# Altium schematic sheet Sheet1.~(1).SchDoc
size A4
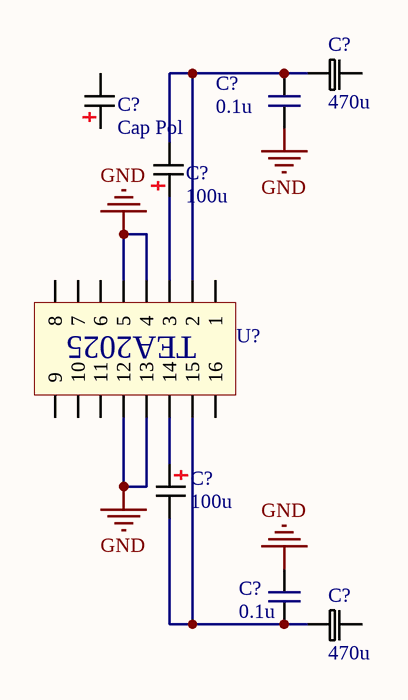
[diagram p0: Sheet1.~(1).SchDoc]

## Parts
(Parts that share a designator on the sheet are numbered #1, #2 ... from top to bottom, then left to right.)
C?#1  470u  [CF0.1]
C?#2  Cap Pol  [CF0.1]
C?#3  0.1u  [RAD0.1]
C?#4  100u  [CF0.1]
C?#5  100u  [CF0.1]
C?#6  0.1u  [RAD0.1]
C?#7  470u  [CF0.1]
U?  TEA2025  [DIP16]  (value not drawn)

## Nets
GND: C?#3.1 C?#6.2 U?.4 U?.5 U?.12 U?.13
NetC?#1_1: C?#1.1 C?#3.2 C?#4.2 U?.2
NetC?#4_1: C?#4.1 U?.3
NetC?#5_1: C?#5.1 U?.14
NetC?#5_2: C?#5.2 C?#6.1 C?#7.1 U?.15

Not connected (* = marked no-connect by the designer): C?#1 2; C?#2 1 2; C?#7 2; U? 1 6 7 8 9 10 11 16

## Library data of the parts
C?#1 C?#7 = CF
C?#3 C?#6 = Cap
C?#4 C?#5 = Cap Pol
